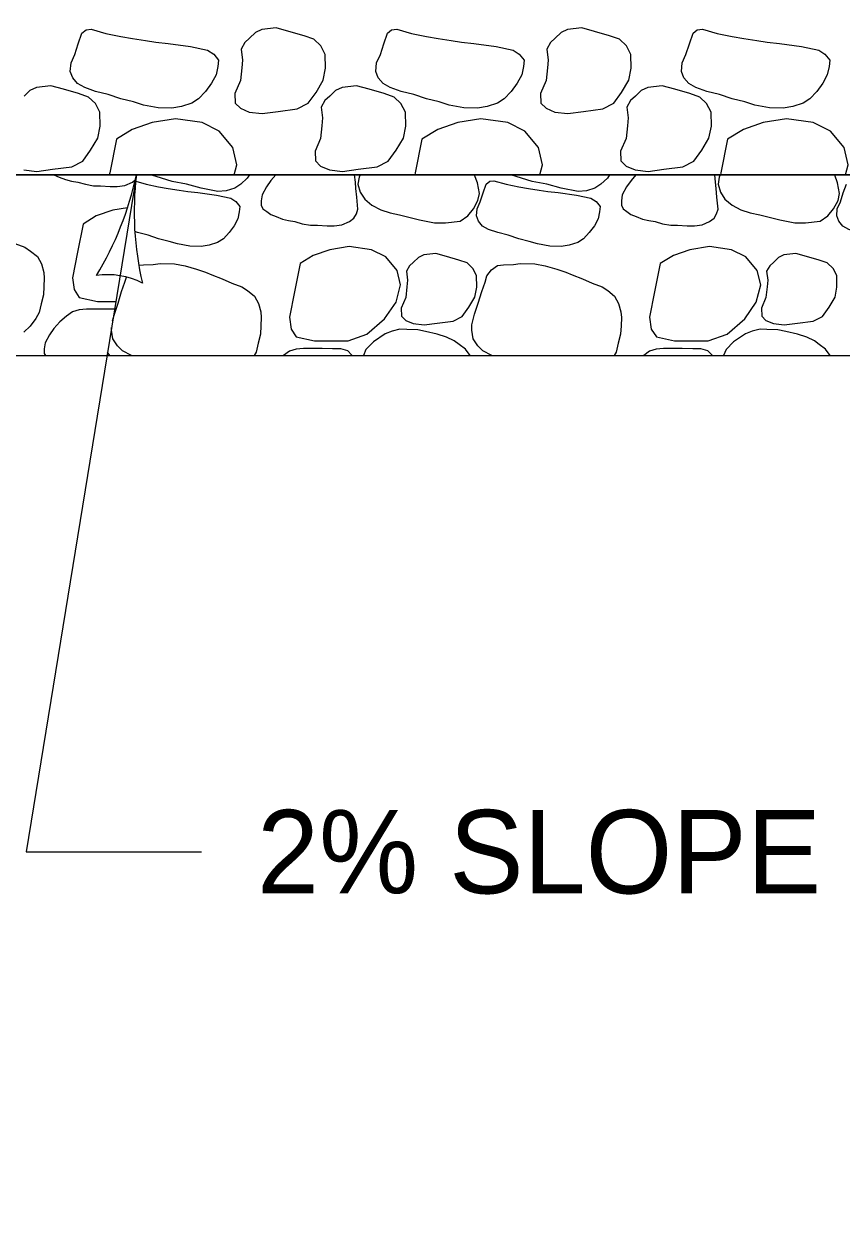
# Model space of a CAD drawing. Extents: x 49991.4 to 50021, y 49987.6 to 50011.4.
# Drawn here: x 50005.238 to 50005.826, y 49991.901 to 49992.771 of the extents above; entities that cross this region are included whole.
import ezdxf

# ---------------------------------------------------------------- set-up
doc = ezdxf.new("R2010")
doc.units = 0
for name, color, linetype in [('Level 1', 7, 'Continuous'), ('Level 2', 7, 'Continuous'), ('Level 3', 7, 'Continuous')]:
    doc.layers.add(name, color=color, linetype=linetype)

msp = doc.modelspace()

# ---------------------------------------------------------------- linework, layer by layer
at = {"layer": 'Level 1'}
for p, q in [((50005.14648, 49992.66299), (50006.02871, 49992.66299)), ((50005.3201, 49992.59799), (50005.32343, 49992.59842)), ((50005.14648, 49992.53299), (50006.02871, 49992.53299)), ((50005.29933, 49992.53299), (50005.29755, 49992.53542))]:
    msp.add_line(p, q, dxfattribs=at)
for points in [[(50006.83405, 49992.91549), (50006.29385, 49992.78039), (50006.11925, 49992.71859), (50006.02871, 49992.66299), (50005.14648, 49992.66299), (50002.16918, 49991.17439), (50001.49048, 49991.20519)], [(50005.23733, 49992.66659), (50005.24669, 49992.66547), (50005.25801, 49992.66704), (50005.2718, 49992.66883), (50005.27968, 49992.67286), (50005.28534, 49992.6807), (50005.29051, 49992.68943), (50005.29224, 49992.69816), (50005.29199, 49992.70801), (50005.28879, 49992.71428), (50005.28387, 49992.71898), (50005.27673, 49992.72145), (50005.26589, 49992.72458), (50005.25678, 49992.72705), (50005.24644, 49992.72593), (50005.24176, 49992.72369), (50005.23758, 49992.71966)], [(50005.38877, 49992.66299), (50005.39069, 49992.6702), (50005.38773, 49992.68274), (50005.37789, 49992.69438), (50005.36558, 49992.70065), (50005.34637, 49992.70334), (50005.32963, 49992.70065), (50005.31535, 49992.69572), (50005.30394, 49992.68878), (50005.2991, 49992.66437), (50005.29882, 49992.66299)], [(50005.60865, 49992.66299), (50005.61057, 49992.6702), (50005.60762, 49992.68274), (50005.59777, 49992.69438), (50005.58546, 49992.70065), (50005.56626, 49992.70334), (50005.54951, 49992.70065), (50005.53523, 49992.69572), (50005.52382, 49992.68878), (50005.51898, 49992.66437), (50005.5187, 49992.66299)], [(50005.82854, 49992.66299), (50005.83046, 49992.6702), (50005.8275, 49992.68274), (50005.81766, 49992.69438), (50005.80535, 49992.70065), (50005.78614, 49992.70334), (50005.7694, 49992.70065), (50005.75512, 49992.69572), (50005.74371, 49992.68878), (50005.73887, 49992.66437), (50005.73859, 49992.66299)], [(50005.25877, 49992.66299), (50005.25882, 49992.66295), (50005.26272, 49992.66146), (50005.26723, 49992.65959), (50005.27175, 49992.65847), (50005.27626, 49992.65773), (50005.2816, 49992.65624), (50005.28755, 49992.65512), (50005.29247, 49992.65512), (50005.29945, 49992.65474), (50005.30458, 49992.65474), (50005.31012, 49992.65549), (50005.31545, 49992.65773), (50005.31747, 49992.65934)], [(50005.39972, 49992.66299), (50005.39812, 49992.6607), (50005.3934, 49992.65641), (50005.38909, 49992.65343), (50005.38294, 49992.65156), (50005.37698, 49992.651), (50005.36488, 49992.65343), (50005.35441, 49992.65622), (50005.34395, 49992.65828), (50005.33246, 49992.66182), (50005.32859, 49992.66299)], [(50005.41864, 49992.66299), (50005.41515, 49992.65903), (50005.41187, 49992.65436), (50005.40879, 49992.64877), (50005.40817, 49992.64429), (50005.40817, 49992.64112), (50005.4094, 49992.63869), (50005.41207, 49992.63664), (50005.41494, 49992.63459), (50005.41884, 49992.63309), (50005.42336, 49992.63123), (50005.42787, 49992.63011), (50005.43238, 49992.62936), (50005.43772, 49992.62787), (50005.44367, 49992.62675), (50005.44859, 49992.62675), (50005.45557, 49992.62638), (50005.4607, 49992.62638), (50005.46624, 49992.62712), (50005.47157, 49992.62936), (50005.47486, 49992.63197), (50005.4767, 49992.63496), (50005.47773, 49992.63832), (50005.47691, 49992.64709), (50005.47629, 49992.65324), (50005.47588, 49992.65772), (50005.47532, 49992.66299)], [(50005.47932, 49992.66299), (50005.47855, 49992.66145), (50005.47773, 49992.65623), (50005.47937, 49992.65063), (50005.48265, 49992.64559), (50005.48778, 49992.6413), (50005.49414, 49992.63794), (50005.50091, 49992.6357), (50005.50769, 49992.63421), (50005.52205, 49992.63067), (50005.53292, 49992.62861), (50005.54072, 49992.62843), (50005.55118, 49992.62973), (50005.55672, 49992.63365), (50005.56083, 49992.6385), (50005.56411, 49992.64447), (50005.56514, 49992.6497), (50005.5637, 49992.65735), (50005.56165, 49992.66276), (50005.56151, 49992.66299)], [(50005.65884, 49992.66299), (50005.65725, 49992.6607), (50005.65253, 49992.65641), (50005.64822, 49992.65343), (50005.64206, 49992.65156), (50005.63611, 49992.651), (50005.62401, 49992.65343), (50005.61354, 49992.65622), (50005.60308, 49992.65828), (50005.59159, 49992.66182), (50005.58772, 49992.66299)], [(50005.67777, 49992.66299), (50005.67428, 49992.65903), (50005.67099, 49992.65436), (50005.66791, 49992.64877), (50005.6673, 49992.64429), (50005.6673, 49992.64112), (50005.66853, 49992.63869), (50005.6712, 49992.63664), (50005.67407, 49992.63459), (50005.67797, 49992.63309), (50005.68248, 49992.63123), (50005.687, 49992.63011), (50005.69151, 49992.62936), (50005.69685, 49992.62787), (50005.7028, 49992.62675), (50005.70772, 49992.62675), (50005.7147, 49992.62638), (50005.71983, 49992.62638), (50005.72537, 49992.62712), (50005.7307, 49992.62936), (50005.73398, 49992.63197), (50005.73583, 49992.63496), (50005.73686, 49992.63832), (50005.73604, 49992.64709), (50005.73542, 49992.65324), (50005.73501, 49992.65772), (50005.73444, 49992.66299)], [(50005.73844, 49992.66299), (50005.73768, 49992.66145), (50005.73686, 49992.65623), (50005.7385, 49992.65063), (50005.74178, 49992.64559), (50005.74691, 49992.6413), (50005.75327, 49992.63794), (50005.76004, 49992.6357), (50005.76681, 49992.63421), (50005.78118, 49992.63067), (50005.79205, 49992.62861), (50005.79985, 49992.62843), (50005.81031, 49992.62973), (50005.81585, 49992.63365), (50005.81995, 49992.6385), (50005.82324, 49992.64447), (50005.82426, 49992.6497), (50005.82283, 49992.65735), (50005.82078, 49992.66276), (50005.82064, 49992.66299)], [(50005.31788, 49992.65842), (50005.3253, 49992.65623), (50005.33432, 49992.65436), (50005.3413, 49992.65324), (50005.3491, 49992.65212), (50005.35525, 49992.65101), (50005.36264, 49992.65026), (50005.37598, 49992.64839), (50005.38623, 49992.64615), (50005.38993, 49992.64391), (50005.3928, 49992.64018), (50005.39239, 49992.63645), (50005.39136, 49992.63141), (50005.3887, 49992.62638), (50005.385, 49992.62152), (50005.3809, 49992.61705), (50005.3768, 49992.61443), (50005.37064, 49992.61257), (50005.3649, 49992.61145), (50005.35669, 49992.61163), (50005.34787, 49992.61331), (50005.34192, 49992.61518), (50005.33432, 49992.61705), (50005.32673, 49992.61966), (50005.31914, 49992.62152), (50005.31721, 49992.62218)], [(50005.91006, 49992.63359), (50005.90962, 49992.63141), (50005.90695, 49992.62638), (50005.90326, 49992.62152), (50005.89915, 49992.61705), (50005.89505, 49992.61443), (50005.8889, 49992.61257), (50005.88315, 49992.61145), (50005.87494, 49992.61163), (50005.86612, 49992.61331), (50005.86017, 49992.61518), (50005.85258, 49992.61705), (50005.84499, 49992.61966), (50005.8374, 49992.62152), (50005.83083, 49992.62376), (50005.82652, 49992.62619), (50005.82365, 49992.62973), (50005.82221, 49992.63347), (50005.82262, 49992.63869), (50005.82488, 49992.64354), (50005.82693, 49992.65007), (50005.82919, 49992.65642)], [(50005.31187, 49992.63926), (50005.30139, 49992.63758), (50005.28949, 49992.63347), (50005.27998, 49992.62768)], [(50005.27998, 49992.62768), (50005.27595, 49992.60735), (50005.27226, 49992.58906), (50005.27349, 49992.58048), (50005.27718, 49992.57488), (50005.29031, 49992.5719), (50005.30349, 49992.5719)], [(50005.23092, 49992.61354), (50005.2381, 49992.61093), (50005.2422, 49992.60813), (50005.24713, 49992.60421), (50005.25, 49992.59899), (50005.25164, 49992.59283), (50005.25205, 49992.58873), (50005.25184, 49992.58275), (50005.25143, 49992.57678), (50005.24979, 49992.57025), (50005.24836, 49992.56391), (50005.24589, 49992.5598), (50005.242, 49992.55421), (50005.23728, 49992.54991)], [(50005.43611, 49992.59932), (50005.43207, 49992.57898), (50005.42838, 49992.5607), (50005.42961, 49992.55211), (50005.4333, 49992.54652), (50005.44643, 49992.54353), (50005.47065, 49992.54353), (50005.48419, 49992.54838), (50005.49691, 49992.55958), (50005.50512, 49992.57152), (50005.5084, 49992.58383), (50005.50594, 49992.59428), (50005.49773, 49992.60399), (50005.48747, 49992.60921), (50005.47147, 49992.61145), (50005.45751, 49992.60921), (50005.44561, 49992.60511), (50005.43611, 49992.59932)], [(50005.69523, 49992.59932), (50005.6912, 49992.57898), (50005.68751, 49992.5607), (50005.68874, 49992.55211), (50005.69243, 49992.54652), (50005.70556, 49992.54353), (50005.72977, 49992.54353), (50005.74332, 49992.54838), (50005.75604, 49992.55958), (50005.76424, 49992.57152), (50005.76753, 49992.58383), (50005.76506, 49992.59428), (50005.75686, 49992.60399), (50005.7466, 49992.60921), (50005.73059, 49992.61145), (50005.71664, 49992.60921), (50005.70474, 49992.60511), (50005.69523, 49992.59932)], [(50005.52512, 49992.60548), (50005.52122, 49992.60361), (50005.51774, 49992.60025), (50005.51486, 49992.59764), (50005.51261, 49992.59372), (50005.51343, 49992.58719), (50005.51302, 49992.58253), (50005.5122, 49992.57488), (50005.50891, 49992.56723), (50005.50912, 49992.56144), (50005.5122, 49992.55827), (50005.51753, 49992.55603), (50005.52533, 49992.5551), (50005.53477, 49992.5564), (50005.54626, 49992.5579), (50005.55282, 49992.56126), (50005.55754, 49992.56779), (50005.56185, 49992.57506), (50005.56329, 49992.58234), (50005.56308, 49992.59055), (50005.56041, 49992.59577), (50005.55631, 49992.59969), (50005.55036, 49992.60175), (50005.54133, 49992.60436), (50005.53374, 49992.60641), (50005.52512, 49992.60548)], [(50005.32343, 49992.59842), (50005.33041, 49992.59861), (50005.33533, 49992.59917), (50005.3458, 49992.59898), (50005.35339, 49992.59749), (50005.3616, 49992.59525), (50005.36816, 49992.59301), (50005.37268, 49992.59115), (50005.38006, 49992.58816), (50005.38704, 49992.58517), (50005.39422, 49992.58256), (50005.39832, 49992.57976), (50005.40325, 49992.57584), (50005.40612, 49992.57062), (50005.40776, 49992.56446), (50005.40817, 49992.56036), (50005.40797, 49992.55439), (50005.40756, 49992.54842), (50005.40592, 49992.54189), (50005.40448, 49992.53554), (50005.40295, 49992.53299)], [(50005.57402, 49992.53299), (50005.56758, 49992.53647), (50005.56389, 49992.54002), (50005.56061, 49992.54506), (50005.55958, 49992.55121), (50005.55958, 49992.55513), (50005.56163, 49992.56278), (50005.5643, 49992.57081), (50005.56676, 49992.57902), (50005.56922, 49992.58592), (50005.57045, 49992.5904), (50005.57374, 49992.59469), (50005.57825, 49992.59786), (50005.58256, 49992.59842)], [(50005.58256, 49992.59842), (50005.58954, 49992.59861), (50005.59446, 49992.59917), (50005.60492, 49992.59898), (50005.61252, 49992.59749), (50005.62072, 49992.59525), (50005.62729, 49992.59301), (50005.6318, 49992.59115), (50005.63919, 49992.58816), (50005.64617, 49992.58517), (50005.65335, 49992.58256), (50005.65745, 49992.57976), (50005.66238, 49992.57584), (50005.66525, 49992.57062), (50005.66689, 49992.56446), (50005.6673, 49992.56036), (50005.66709, 49992.55439), (50005.66668, 49992.54842), (50005.66504, 49992.54189), (50005.66361, 49992.53554), (50005.66208, 49992.53299)], [(50005.30123, 49992.55805), (50005.3025, 49992.56278), (50005.30517, 49992.57081), (50005.30763, 49992.57902), (50005.3101, 49992.58592), (50005.3111, 49992.58956)], [(50005.27708, 49992.56597), (50005.27236, 49992.56447), (50005.26805, 49992.5613), (50005.26313, 49992.5572), (50005.25903, 49992.55253), (50005.25574, 49992.54787), (50005.25266, 49992.54227), (50005.25205, 49992.53779), (50005.25205, 49992.53462), (50005.25287, 49992.53299)], [(50005.30259, 49992.56636), (50005.29575, 49992.56653), (50005.28816, 49992.56653), (50005.28242, 49992.56653), (50005.27708, 49992.56597)], [(50005.3149, 49992.53299), (50005.30845, 49992.53647), (50005.30476, 49992.54002), (50005.30148, 49992.54506), (50005.30045, 49992.55121), (50005.30045, 49992.55325)], [(50005.55846, 49992.53299), (50005.55508, 49992.5376), (50005.55057, 49992.54096), (50005.54708, 49992.54376), (50005.54154, 49992.54618), (50005.53477, 49992.54842), (50005.52636, 49992.55047), (50005.52082, 49992.55159), (50005.51281, 49992.55178), (50005.50789, 49992.55215), (50005.50235, 49992.55066), (50005.49743, 49992.54861)], [(50005.81759, 49992.53299), (50005.81421, 49992.5376), (50005.8097, 49992.54096), (50005.80621, 49992.54376), (50005.80067, 49992.54618), (50005.7939, 49992.54842), (50005.78548, 49992.55047), (50005.77994, 49992.55159), (50005.77194, 49992.55178), (50005.76702, 49992.55215), (50005.76148, 49992.55066), (50005.75655, 49992.54861)], [(50005.49743, 49992.54861), (50005.48881, 49992.54282), (50005.48347, 49992.53741), (50005.48168, 49992.53299)], [(50005.75655, 49992.54861), (50005.74794, 49992.54282), (50005.7426, 49992.53741), (50005.7408, 49992.53299)], [(50005.4332, 49992.5376), (50005.42848, 49992.53611), (50005.42426, 49992.53299)], [(50005.47361, 49992.53299), (50005.47321, 49992.53368), (50005.47034, 49992.53648), (50005.46542, 49992.53778), (50005.45947, 49992.53797), (50005.45188, 49992.53816), (50005.44428, 49992.53816), (50005.43854, 49992.53816), (50005.4332, 49992.5376)], [(50005.69233, 49992.5376), (50005.68761, 49992.53611), (50005.68339, 49992.53299)], [(50005.73274, 49992.53299), (50005.73234, 49992.53368), (50005.72947, 49992.53648), (50005.72455, 49992.53778), (50005.71859, 49992.53797), (50005.711, 49992.53816), (50005.70341, 49992.53816), (50005.69767, 49992.53816), (50005.69233, 49992.5376)]]:
    msp.add_lwpolyline(points, dxfattribs=at)
for points in [[(50005.27916, 49992.76493), (50005.28211, 49992.76739), (50005.2858, 49992.76784), (50005.29639, 49992.76471), (50005.30722, 49992.76247), (50005.31559, 49992.76112), (50005.32495, 49992.75978), (50005.33234, 49992.75844), (50005.3412, 49992.75754), (50005.35721, 49992.7553), (50005.36952, 49992.75262), (50005.37395, 49992.74993), (50005.3774, 49992.74545), (50005.3769, 49992.74097), (50005.37567, 49992.73493), (50005.37247, 49992.72888), (50005.36804, 49992.72306), (50005.36311, 49992.71769), (50005.35819, 49992.71455), (50005.35081, 49992.71231), (50005.34391, 49992.71097), (50005.33406, 49992.71119), (50005.32348, 49992.71321), (50005.31634, 49992.71545), (50005.30722, 49992.71769), (50005.29811, 49992.72082), (50005.28901, 49992.72306), (50005.28112, 49992.72575), (50005.27596, 49992.72866), (50005.27251, 49992.73291), (50005.27078, 49992.73739), (50005.27128, 49992.74366), (50005.27398, 49992.74948), (50005.27645, 49992.75732)], [(50005.40867, 49992.76754), (50005.40399, 49992.7653), (50005.39981, 49992.76127), (50005.39636, 49992.75814), (50005.39365, 49992.75343), (50005.39463, 49992.7456), (50005.39414, 49992.74), (50005.39316, 49992.73082), (50005.38922, 49992.72164), (50005.38947, 49992.7147), (50005.39316, 49992.71089), (50005.39956, 49992.70821), (50005.40892, 49992.70709), (50005.42024, 49992.70865), (50005.43403, 49992.71044), (50005.44191, 49992.71448), (50005.44757, 49992.72231), (50005.45274, 49992.73105), (50005.45447, 49992.73978), (50005.45422, 49992.74963), (50005.45102, 49992.7559), (50005.4461, 49992.7606), (50005.43896, 49992.76306), (50005.42812, 49992.7662), (50005.41901, 49992.76866)], [(50005.49904, 49992.76493), (50005.50199, 49992.76739), (50005.50569, 49992.76784), (50005.51628, 49992.76471), (50005.52711, 49992.76247), (50005.53548, 49992.76112), (50005.54484, 49992.75978), (50005.55222, 49992.75844), (50005.56109, 49992.75754), (50005.57709, 49992.7553), (50005.5894, 49992.75262), (50005.59384, 49992.74993), (50005.59728, 49992.74545), (50005.59679, 49992.74097), (50005.59556, 49992.73493), (50005.59236, 49992.72888), (50005.58793, 49992.72306), (50005.583, 49992.71769), (50005.57808, 49992.71455), (50005.57069, 49992.71231), (50005.5638, 49992.71097), (50005.55395, 49992.71119), (50005.54336, 49992.71321), (50005.53622, 49992.71545), (50005.52711, 49992.71769), (50005.518, 49992.72082), (50005.50889, 49992.72306), (50005.50101, 49992.72575), (50005.49584, 49992.72866), (50005.49239, 49992.73291), (50005.49067, 49992.73739), (50005.49116, 49992.74366), (50005.49387, 49992.74948), (50005.49633, 49992.75732)], [(50005.62856, 49992.76754), (50005.62388, 49992.7653), (50005.61969, 49992.76127), (50005.61624, 49992.75814), (50005.61354, 49992.75343), (50005.61452, 49992.7456), (50005.61403, 49992.74), (50005.61304, 49992.73082), (50005.6091, 49992.72164), (50005.60935, 49992.7147), (50005.61304, 49992.71089), (50005.61945, 49992.70821), (50005.6288, 49992.70709), (50005.64013, 49992.70865), (50005.65392, 49992.71044), (50005.66179, 49992.71448), (50005.66746, 49992.72231), (50005.67263, 49992.73105), (50005.67435, 49992.73978), (50005.67411, 49992.74963), (50005.6709, 49992.7559), (50005.66598, 49992.7606), (50005.65884, 49992.76306), (50005.64801, 49992.7662), (50005.6389, 49992.76866)], [(50005.71893, 49992.76493), (50005.72188, 49992.76739), (50005.72557, 49992.76784), (50005.73616, 49992.76471), (50005.74699, 49992.76247), (50005.75536, 49992.76112), (50005.76472, 49992.75978), (50005.77211, 49992.75844), (50005.78097, 49992.75754), (50005.79698, 49992.7553), (50005.80929, 49992.75262), (50005.81372, 49992.74993), (50005.81717, 49992.74545), (50005.81667, 49992.74097), (50005.81544, 49992.73493), (50005.81224, 49992.72888), (50005.80781, 49992.72306), (50005.80288, 49992.71769), (50005.79796, 49992.71455), (50005.79058, 49992.71231), (50005.78368, 49992.71097), (50005.77383, 49992.71119), (50005.76325, 49992.71321), (50005.75611, 49992.71545), (50005.74699, 49992.71769), (50005.73788, 49992.72082), (50005.72878, 49992.72306), (50005.72089, 49992.72575), (50005.71573, 49992.72866), (50005.71228, 49992.73291), (50005.71055, 49992.73739), (50005.71105, 49992.74366), (50005.71375, 49992.74948), (50005.71622, 49992.75732)], [(50005.46633, 49992.72593), (50005.46165, 49992.72369), (50005.45746, 49992.71966), (50005.45401, 49992.71652), (50005.4513, 49992.71182), (50005.45229, 49992.70398), (50005.4518, 49992.69838), (50005.45081, 49992.6892), (50005.44687, 49992.68002), (50005.44712, 49992.67308), (50005.45081, 49992.66927), (50005.45721, 49992.66659), (50005.46657, 49992.66547), (50005.4779, 49992.66704), (50005.49168, 49992.66883), (50005.49956, 49992.67286), (50005.50523, 49992.6807), (50005.5104, 49992.68943), (50005.51212, 49992.69816), (50005.51187, 49992.70801), (50005.50867, 49992.71428), (50005.50375, 49992.71898), (50005.49661, 49992.72145), (50005.48577, 49992.72458), (50005.47667, 49992.72705)], [(50005.68621, 49992.72593), (50005.68153, 49992.72369), (50005.67735, 49992.71966), (50005.6739, 49992.71652), (50005.67119, 49992.71182), (50005.67217, 49992.70398), (50005.67168, 49992.69838), (50005.6707, 49992.6892), (50005.66676, 49992.68002), (50005.667, 49992.67308), (50005.6707, 49992.66927), (50005.6771, 49992.66659), (50005.68646, 49992.66547), (50005.69778, 49992.66704), (50005.71157, 49992.66883), (50005.71945, 49992.67286), (50005.72511, 49992.6807), (50005.73028, 49992.68943), (50005.73201, 49992.69816), (50005.73176, 49992.70801), (50005.72856, 49992.71428), (50005.72364, 49992.71898), (50005.7165, 49992.72145), (50005.70566, 49992.72458), (50005.69655, 49992.72705)], [(50001.49048, 49991.20519), (50001.49048, 49991.07519), (50002.16918, 49991.04439), (50005.14648, 49992.53299), (50006.02871, 49992.53299), (50006.02871, 49992.66299), (50005.14648, 49992.66299), (50002.16918, 49991.17439)], [(50005.57006, 49992.65642), (50005.57252, 49992.65847), (50005.5756, 49992.65884), (50005.58442, 49992.65623), (50005.59345, 49992.65436), (50005.60043, 49992.65324), (50005.60822, 49992.65212), (50005.61438, 49992.65101), (50005.62177, 49992.65026), (50005.6351, 49992.64839), (50005.64536, 49992.64615), (50005.64906, 49992.64391), (50005.65193, 49992.64018), (50005.65152, 49992.63645), (50005.65049, 49992.63141), (50005.64782, 49992.62638), (50005.64413, 49992.62152), (50005.64003, 49992.61705), (50005.63592, 49992.61443), (50005.62977, 49992.61257), (50005.62402, 49992.61145), (50005.61582, 49992.61163), (50005.60699, 49992.61331), (50005.60104, 49992.61518), (50005.59345, 49992.61705), (50005.58586, 49992.61966), (50005.57827, 49992.62152), (50005.5717, 49992.62376), (50005.56739, 49992.62619), (50005.56452, 49992.62973), (50005.56308, 49992.63347), (50005.56349, 49992.63869), (50005.56575, 49992.64354), (50005.5678, 49992.65007)], [(50005.78425, 49992.60548), (50005.78035, 49992.60361), (50005.77686, 49992.60025), (50005.77399, 49992.59764), (50005.77173, 49992.59372), (50005.77255, 49992.58719), (50005.77214, 49992.58253), (50005.77132, 49992.57488), (50005.76804, 49992.56723), (50005.76825, 49992.56144), (50005.77132, 49992.55827), (50005.77666, 49992.55603), (50005.78446, 49992.5551), (50005.79389, 49992.5564), (50005.80538, 49992.5579), (50005.81195, 49992.56126), (50005.81667, 49992.56779), (50005.82098, 49992.57506), (50005.82241, 49992.58234), (50005.82221, 49992.59055), (50005.81954, 49992.59577), (50005.81544, 49992.59969), (50005.80949, 49992.60175), (50005.80046, 49992.60436), (50005.79287, 49992.60641)]]:
    msp.add_lwpolyline(points, close=True, dxfattribs=at)
at = {"layer": 'Level 3'}
for p, q in [((50005.31833, 49992.66299), (50005.23902, 49992.17621)), ((50005.23902, 49992.17621), (50005.36514, 49992.17621))]:
    msp.add_line(p, q, dxfattribs=at)
for centre, radius, start, end in [((50005.0905, 49992.71176), 0.233, 328.66915, 347.919), ((50005.53905, 49992.63631), 0.22232, 173.10679, 193.2903), ((50005.29772, 49992.53645), 0.05477, 62.88513, 98.60749)]:
    msp.add_arc(centre, radius, start, end, dxfattribs=at)

# ---------------------------------------------------------------- texts
at = {"layer": 'Level 2'}
msp.add_text('2% SLOPE', height=0.06, dxfattribs=at).set_placement((50005.40514, 49992.14621))

doc.saveas('drawing.dxf')
